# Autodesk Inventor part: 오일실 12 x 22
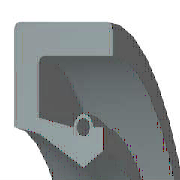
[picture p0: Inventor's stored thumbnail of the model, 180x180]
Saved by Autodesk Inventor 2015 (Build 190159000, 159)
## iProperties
IsCustomPart: 0
Created: 2015-10
Part Number: 오일실 12 x 22
Material: 고무
Description: 오일-실
Document SubType Name: Modeling
Standard: KS B 2804
Designer: mdu
Standards Organization: KS
Language: ko-KR
Size Designation: S - 12 22 7
Categories: <MemberInstance><Categories><Category DisplayName="샤프트 부품" InternalName="7f7aeb1f-a693-4053-b835-cee3144e0d98" Mnemonic="SHFT"><Category DisplayName="실링" Intern
Density: 0.93 g/cm^3
Appearance: 고무 - 검은색 - 버전 1.1
Author: mdu
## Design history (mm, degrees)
revolve "본체" stored, may be unused: angle "d17" = 90 deg
revolve "스프링1" stored, may be unused: angle "d18" = 90 deg
body "Solid1"
sketch "스케치1"
  geometry: L1 (0, 11)-(7, 11); L2 (7, 11)-(7, 9.75); L3 (7, 9.75)-(1.75, 9.75); L4 (0, 11)-(0, 8.1); L5 (0, 8.1)-(1.75, 7.75); L6 (1.75, 7.75)-(4.9, 6); L7 (4.9, 6)-(0, 6); L8 (6.3, 6.875)-(6.3, 8.1); L9 (0, 0)-(9.586, 0) reference; L10 (4.9, 6)-(6.3, 6.875); L11 (0, 18)-(0, -3) reference; L12 (-1.917, 0)-(11.503, 0) reference; L13 (4.2, 8.1)-(1.75, 8.59); L14 (1.75, 8.59)-(1.75, 9.75); L15 (6.3, 8.1)-(5.6, 8.1); C1 r 0.455 at (4.9, 8.1); A1 r 0.7 centre (4.9, 8.1) between (5.6, 8.1) and (4.2, 8.1)
  constraints: 26 end point, 5 horizontal alignment, 4 perpendicular, 2 centre point, 2 collinear, 2 horizontal, 2 parallel, 2 point on circle, 2 point on line, 2 vertical alignment, 1 coincident
  dimensions: "d0" = 22 diameter of L1 L9 (= SD2); "d1" = 13.75 diameter of L8.start L9 (= ABDM); "d2" = 1.25 distance of L1.end L2.end (computed from SD); "d3" = 0.91 diameter of C1 (= SPDI); "d4" = 1.4 diameter of A1 (= SPDA); "d5" = 12 diameter of L6.end L9 (= NND); "d6" = 15.5 diameter of L5.end L9 (= TKDM); "d7" = 16.2 diameter of L4.end L9 (= HLDM); "d8" = 4.9 distance from line of C1.centre L4 (= SPDST); "d9" = 6.3 distance between parallel lines of L8 L4 (= SDI); "d10" = 7 distance between parallel lines of L2 L4 (= SWDT); "d12" = 1.75 distance between parallel lines of L14 L4 (= SD)
fillet "모깎기1" dims "d11" = 0.3 (= RR)
other parameters: "SD2" = 22 [user parameter; used in 1 equation term], "SWDT" = 7 [user parameter; used in 1 equation term], "RR" = 0.3 [user parameter; used in 1 equation term], "SD" = 1.75 [user parameter; used in 2 equation terms], "NND" = 12 [user parameter; used in 1 equation term], "SPDA" = 1.4 [user parameter; used in 1 equation term], "SPDI" = 0.91 [user parameter; used in 1 equation term], "TKDM" = 15.5 [user parameter; used in 1 equation term], "HLDM" = 16.2 [user parameter; used in 1 equation term], "ABDM" = 13.75 [user parameter; used in 1 equation term], "SDI" = 6.3 [user parameter; used in 1 equation term], "SPDST" = 4.9 [user parameter; used in 1 equation term], "d13" = 0, "d14" = 0, "d15" = 0, "LAB" = 0.35 [user parameter]
